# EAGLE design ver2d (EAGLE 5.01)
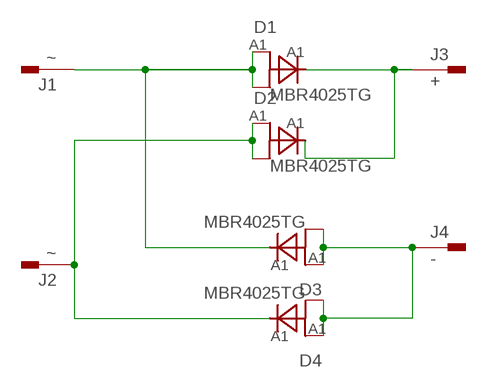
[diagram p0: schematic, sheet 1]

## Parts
D1  MBR4025TG  [TO220ABS]
D2  MBR4025TG  [TO220ABS]
D3  MBR4025TG  [TO220ABS]
D4  MBR4025TG  [TO220ABS]
J1  ~  PIN2F061.200  [F061.200]
J2  ~  PIN2F061.200  [F061.200]
J3  +  PIN2F061.200  [F061.200]
J4  -  PIN2F061.200  [F061.200]

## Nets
N$2: D1.A1 D1.A2 D3.C(K) J1.1A
N$3: D2.A1 D2.A2 D4.C(K) J2.1A
N$4: D3.A1 D3.A2 D4.A1 D4.A2 J4.1A
N$6: D1.C(K) D2.C(K) J3.1A
Unconnected: J1.1B(1.1) J2.1B(1.1) J3.1B(1.1) J4.1B(1.1)

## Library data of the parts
D1-D4 = diode:MBR4025TG
J1-J4 = con-faston:PIN2: Flachstecker Typ Tyco/Electronics/AMP TAB, FASTON

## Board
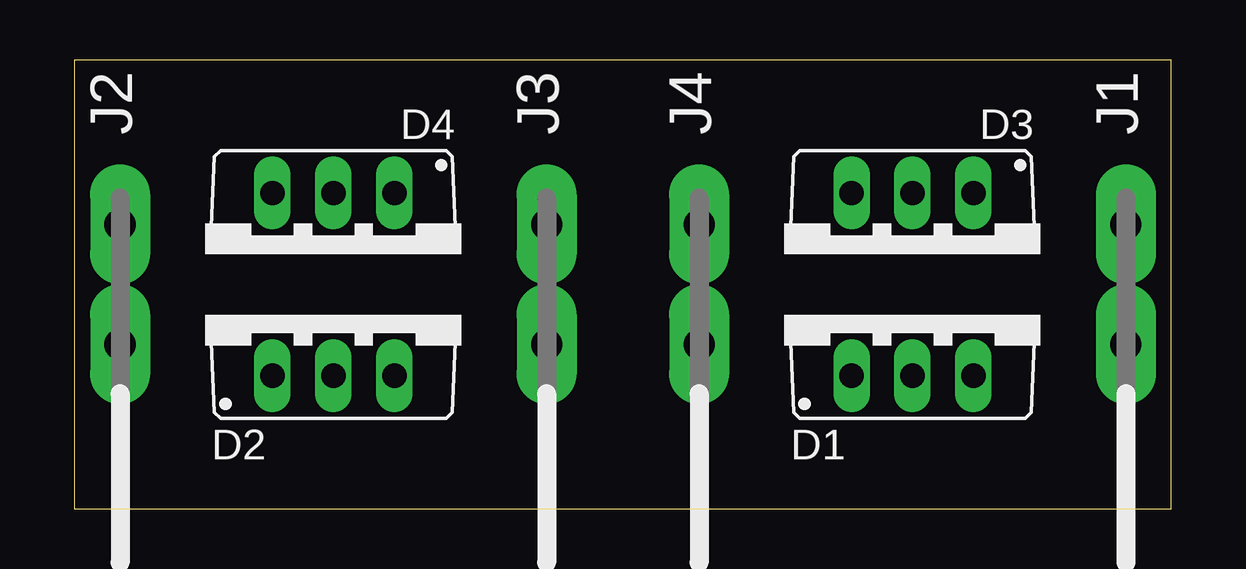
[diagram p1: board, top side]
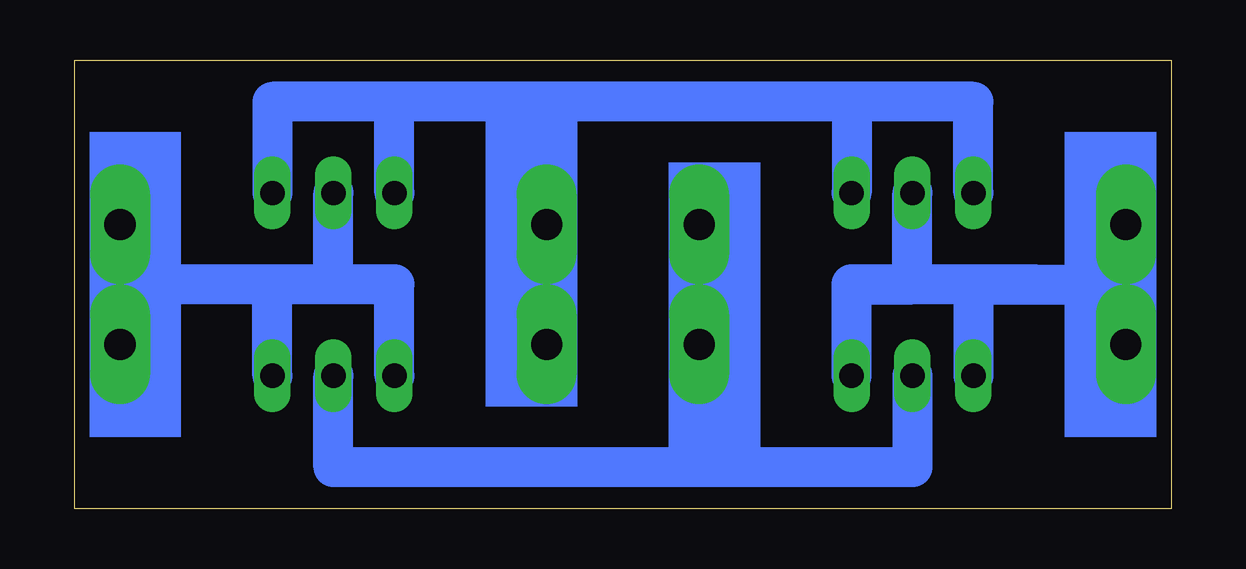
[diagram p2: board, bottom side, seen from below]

Size 45.7 x 18.72 mm. Coordinates in mm from the lower left corner, seen from the top.
Outline: 0,0 45.7,0 45.7,18.72 0,18.72 0,0
Copper layers (1*16): Top 0.035mm / dielectric 1.5mm / Bottom 0.035mm
Design rules "default": minimum track width 10mil, minimum drill 24mil, track to track 8mil, track to pad 8mil, pad to pad 8mil, via to via 8mil, smd to smd 8mil, copper to edge 40mil, drill to drill 8mil, minimum pad ring 10mil, minimum via ring 8mil, stop-mask expansion 4mil, vias tented up to drill 0mil, thermal gap 10mil

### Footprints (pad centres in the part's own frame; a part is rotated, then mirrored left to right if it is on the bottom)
TO220ABS = drill 1.016 long: A1 -2.54,-2.54; A2 2.54,-2.54; C 0,-2.54
F061.200 = drill 1.3 pad 2.5 long: 1A -2.5,0; 1B 2.5,0

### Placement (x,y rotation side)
D1  34.92,8.09 0 top
D2  10.79,8.09 0 top
D3  34.92,10.63 180 top
D4  10.79,10.63 180 top
J1  43.81,9.36 270 top
J2  1.9,9.36 270 top
J3  19.68,9.36 270 top
J4  26.03,9.36 270 top

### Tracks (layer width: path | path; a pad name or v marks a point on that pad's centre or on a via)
N$1
  Bottom 0.406: 3.17,9.36 8.25,9.36 | 10.79,11.9 10.79,9.36 8.25,9.36 | 8.25,9.36 8.25,6.82 | 8.25,9.36 13.33,9.36 13.33,6.82
N$2
  Bottom 0.254: 43.81,9.36 J1.1A
  Bottom 1.676: D1.A1 32.38,9.36 34.92,9.36 | 34.92,9.36 37.46,9.36 | 34.92,9.36 D3.C | 37.46,9.36 43.81,9.36 | D1.A2 37.46,9.36
N$3
  Bottom 0.254: 13.33,8.09 D2.A2 | 1.9,9.36 J2.1A | 3.17,8.09 1.9,9.36 | 1.9,11.9 3.17,10.63 1.9,9.36
  Bottom 1.676: 8.25,9.36 13.33,9.36 | D4.C 10.79,9.36 13.33,9.36 | D2.A2 13.33,8.09 13.33,9.36 | 8.25,9.36 1.9,9.36 | 8.25,9.36 D2.A1 | 5.71,9.36 8.25,9.36
N$4
  Bottom 1.676: 13.33,16.98 D4.A1 | 26.03,16.98 32.38,16.98 | 32.38,16.98 37.46,16.98 D3.A1 | D3.A2 32.38,16.98 | 13.33,16.98 8.25,16.98 D4.A2 | 13.33,16.98 26.03,16.98 | 26.03,16.98 J4.1A
N$6
  Bottom 1.676: 19.68,1.74 34.92,1.74 D1.C | 19.68,1.74 10.79,1.74 D2.C | 19.68,1.74 J3.1A
(copper drawn outside any net)
  shapes: Bottom area x5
